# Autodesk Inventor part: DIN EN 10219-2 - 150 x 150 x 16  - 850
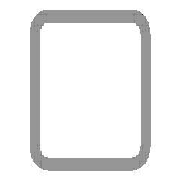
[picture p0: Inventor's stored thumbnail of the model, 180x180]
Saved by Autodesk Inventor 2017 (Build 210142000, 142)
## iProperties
Created: 2017-11
Part Number: DIN EN 10219-2 - 150 x 150 x 16  - 850
Material: Steel, Mild
Description: Cold formed welded structural hollow sections of non-alloy and fine grain structural steel
Document SubType Name: Modeling
Standard: DIN
Designer: iusti
Standard Revision: 2006-07
Standards Organization: DIN
Language: en-US
Size Designation: 150 x 150 x 16
Categories: <MemberInstance><Categories><Category DisplayName="Structural Shapes" InternalName="089c4875-fa83-4c05-b084-43b9cc11f5ed" Mnemonic="GRDR"><CategoryParameter Dis
Stock Number: 150 x 150 x 16
Mass: 49891.9 g
Surface Area: 8094.11 cm^2
Volume: 6355.65 cm^3
Density: 7.85 g/cm^3
Appearance: Semi-Polished
_CCFamilyMember: 76
_CCFamilyDisplayName: DIN EN 10219-2 (Square Hollow Section - Cold Formed) - Cold formed welded structural hollow sections of non-alloy and fine grain structural steel
_FrameMemberDoc: Frame Member File
_Version: 15.0.0
_GetPNFromCC: 1
IsCustomPart: 1
G_L: 850.000 mm
G_W: 150.000 mm
G_H: 150.000 mm
+FD70130C-4790-491E-B60B-C0D4A205CCEB+CUTDETAIL1: Cut
+AC41B5F9-E44C-4FA3-89BE-A85ECCB405C1+CUTDETAIL2: Cut
Author: iusti
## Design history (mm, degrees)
node "Start plane"
node "End plane"
sketch "Sketch"
  geometry: L1 (-75, -27)-(-75, 27); L2 (-27, 75)-(27, 75); L3 (75, 27)-(75, -27); L4 (27, -75)-(-27, -75); L5 (-27, 59)-(27, 59); L6 (59, 27)-(59, -27); L7 (27, -59)-(-27, -59); L8 (-59, -27)-(-59, 27); L9 (0, 153.918)-(0, -153.918) reference; L10 (-153.918, 0)-(153.918, 0) reference; A1 r 48 centre (-27, -27) between (-75, -27) and (-27, -75); A2 r 48 centre (-27, 27) between (-27, 75) and (-75, 27); A3 r 48 centre (27, 27) between (75, 27) and (27, 75); A4 r 48 centre (27, -27) between (27, -75) and (75, -27); A5 r 32 centre (-27, 27) between (-27, 59) and (-59, 27); A6 r 32 centre (27, 27) between (59, 27) and (27, 59); A7 r 32 centre (27, -27) between (27, -59) and (59, -27); A8 r 32 centre (-27, -27) between (-59, -27) and (-27, -59)
  constraints: 16 end point, 16 point on circle, 8 centre point, 8 tangent, 4 parallel, 3 equal radius, 2 perpendicular, 7 other
  dimensions: "d7" = 48 radius of A1 (= G_IR); "d10" = 150 distance between parallel lines of L2 L4 (= G_H); "d11" = 150 distance between parallel lines of L1 L3 (= G_W); "d12" = 16 distance between parallel lines of L3 L6 (= G_T); "d15" = 75 distance between parallel lines of L2 L10 (= 0.5 x d10); "d16" = 75 distance between parallel lines of L9 L3 (= 0.5 x d11)
extrude "Body" new body sketch "Sketch" stored distance "d3" = 850 (= G_L); taper "d4" = 0 deg
node "Driven Length"
  sketch "Sketch3"
    geometry: L1 (0, 0)-(10, 0) reference
    constraints: 2 end point, 1 horizontal
  workplane "Work Plane3"
  sketch "Sketch4"
    geometry: L1 (-2, 75)-(12, 75) reference; L2 (-2, 925)-(12, 925) reference
    dimensions: "d18" = 850 distance between parallel lines of L1 L2 (derived)
workplane "Work Plane4"
split "Split1"
workplane "Work Plane5"
split "Split2"
body "Solid1"
other parameters: "G_W" = 150 [user parameter; used in 1 equation term], "G_H" = 150 [user parameter; used in 1 equation term], "G_T" = 16 [user parameter; used in 1 equation term], "G_IR" = 48 [user parameter; used in 1 equation term], "G_L" = 850 (= d18) [user parameter; used in 1 equation term], "G_OFFSET_START" = -75 [user parameter; used in 1 equation term], "G_OFFSET_END" = -75 [user parameter; used in 1 equation term], "d13" = 75 (= -G_OFFSET_START), "d14" = 925 (= G_OFFSET_END + B_L), "d17" = 90 deg
